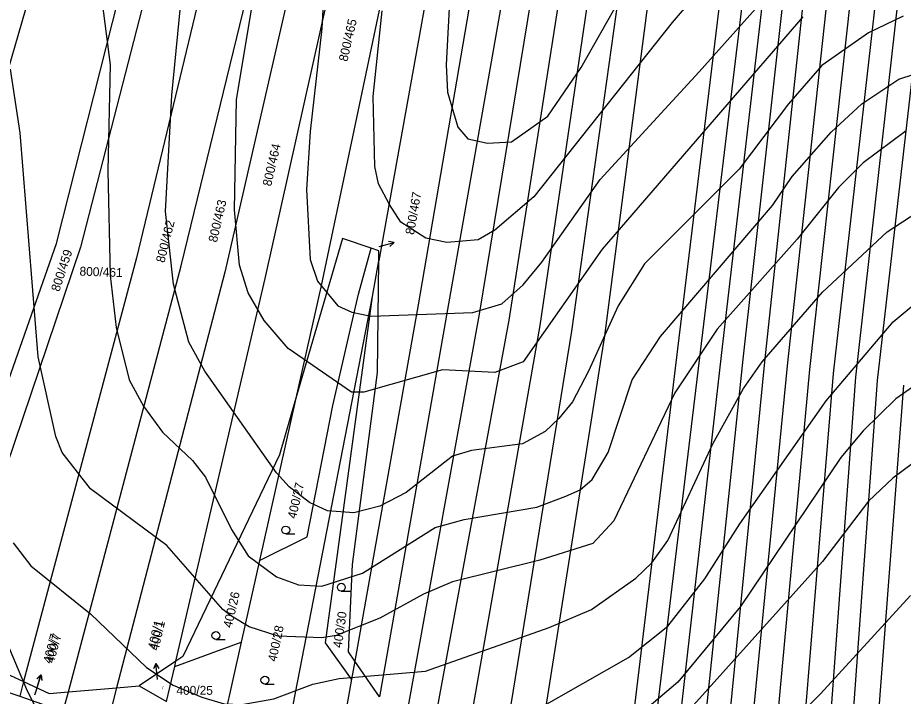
# Model space of a CAD drawing. Extents: x -555860 to -552701, y -1187050 to -1182291.
# Drawn here: x -555176.2 to -555007.3, y -1186234.6 to -1186105 of the extents above; entities that cross this region are included whole.
import ezdxf

# ---------------------------------------------------------------- set-up
doc = ezdxf.new("R2010")
doc.units = 0
for name, color, linetype in [('LEG_2b', 7, 'Continuous'), ('Level 16', 7, 'Continuous'), ('Level 25', 7, 'Continuous'), ('Level 40', 7, 'Continuous'), ('Level 41', 7, 'Continuous'), ('navrh_BV', 7, 'Continuous'), ('stav_BV', 7, 'Continuous')]:
    doc.layers.add(name, color=color, linetype=linetype)

msp = doc.modelspace()

# ---------------------------------------------------------------- linework, layer by layer
at = {"layer": 'Level 16'}
for p, q in [((-555107.26, -1186148.7), (-555104.35, -1186147.96)), ((-555104.35, -1186147.96), (-555105.45, -1186147.72)), ((-555104.35, -1186147.96), (-555105.2, -1186148.69)), ((-555149.86, -1186228.3), (-555150.25, -1186229.34)), ((-555149.54, -1186231.28), (-555149.86, -1186228.3)), ((-555149.86, -1186228.3), (-555149.25, -1186229.24)), ((-555172.61, -1186233.32), (-555171.74, -1186230.45)), ((-555171.74, -1186230.45), (-555172.51, -1186231.26)), ((-555171.74, -1186230.45), (-555171.55, -1186231.55))]:
    msp.add_line(p, q, dxfattribs=at)
for points in [[(-555149.53, -1186231.37), (-555149.54, -1186231.28)], [(-555172.89, -1186234.27), (-555172.61, -1186233.32)]]:
    msp.add_lwpolyline(points, dxfattribs=at)
at = {"layer": 'Level 25'}
for p, q in [((-555125.05, -1186203.58), (-555123.3, -1186203.58)), ((-555114.46, -1186214.51), (-555112.71, -1186214.51)), ((-555138.38, -1186223.73), (-555136.63, -1186223.73)), ((-555129.03, -1186232.24), (-555127.28, -1186232.24))]:
    msp.add_line(p, q, dxfattribs=at)
for centre in [(-555125.05, -1186202.83), (-555114.46, -1186213.76), (-555138.38, -1186222.98), (-555129.03, -1186231.49)]:
    msp.add_circle(centre, 0.75, dxfattribs=at)
at = {"layer": 'Level 40'}
for points in [[(-555026.4, -1186104.85), (-555064.67, -1186149.22), (-555079.79, -1186170.71), (-555085.19, -1186172.79), (-555095.18, -1186172.24), (-555110.15, -1186176.53), (-555112.51, -1186176.53), (-555124.57, -1186168.21), (-555129.15, -1186162.81), (-555132.2, -1186157.54), (-555133.86, -1186152.27), (-555134.83, -1186141.73), (-555134.42, -1186120.66), (-555130.26, -1186095.42)], [(-555216.36, -1186104.57), (-555208.74, -1186114.83), (-555204.3, -1186123.71), (-555203.74, -1186141.73), (-555200.42, -1186171.68), (-555198.48, -1186181.67), (-555194.87, -1186191.65), (-555190.02, -1186201.91), (-555181.14, -1186217.72), (-555174.35, -1186233.52), (-555167.69, -1186246.56), (-555164.64, -1186248.22), (-555153.69, -1186250.72)], [(-555153.69, -1186250.72), (-555143.43, -1186258.34), (-555141.77, -1186258.9), (-555139.13, -1186258.62), (-555137.61, -1186257.65), (-555130.67, -1186247.94), (-555126.51, -1186243.37), (-555120.14, -1186238.93), (-555118.33, -1186238.24), (-555109.78, -1186238.16), (-555102.51, -1186240.96), (-555094.86, -1186242.64), (-555089.83, -1186242.26), (-555085.84, -1186242.07), (-555059.68, -1186227.14), (-555052.19, -1186221.18), (-555045.12, -1186212.17), (-555038.47, -1186201.63), (-555021.97, -1186178.2), (-555009.21, -1186163.08), (-555000.89, -1186156.15)]]:
    msp.add_lwpolyline(points, dxfattribs=at)
at = {"layer": 'Level 41'}
for points in [[(-555090.74, -1186044.12), (-555094.48, -1186114), (-555094.21, -1186119.27), (-555092.26, -1186125.93), (-555090.32, -1186128.14), (-555086.58, -1186128.98), (-555082, -1186128.7), (-555075.07, -1186123.84), (-555068.69, -1186114.55), (-555061.2, -1186101.24)], [(-555117.22, -1186089.32), (-555118.19, -1186107.07), (-555120.41, -1186126.76), (-555121.1, -1186137.85), (-555120.41, -1186151.16), (-555119.03, -1186155.32), (-555115.14, -1186160.03), (-555112.46, -1186161.26), (-555108.77, -1186161.98), (-555089.35, -1186161.28), (-555083.81, -1186159.62), (-555079.79, -1186156.01), (-555076.18, -1186151.72), (-555065.09, -1186135.91), (-555046.23, -1186115.39), (-555027.93, -1186094.87)], [(-555042.49, -1186095.56), (-555051.36, -1186105.96), (-555077.71, -1186139.24), (-555085.19, -1186145.61), (-555088.38, -1186147.42), (-555094.34, -1186147.97), (-555098.36, -1186147.14), (-555103.08, -1186144.09), (-555105.28, -1186140.71), (-555107.38, -1186136.74), (-555108.07, -1186133.41), (-555108.35, -1186120.1), (-555106.69, -1186103.74)], [(-555007.27, -1186104.71), (-555013.92, -1186107.9), (-555022.8, -1186114.14), (-555029.18, -1186121.49), (-555038.6, -1186133.97), (-555056.63, -1186151.99), (-555061.62, -1186160.03), (-555067.31, -1186172.51), (-555070.38, -1186178.34), (-555072.99, -1186181.53), (-555075.58, -1186184.03), (-555079.92, -1186186.38), (-555089.63, -1186187.63), (-555093.23, -1186188.74), (-555102.11, -1186195.67), (-555107.1, -1186198.3), (-555112.09, -1186199.55), (-555117.08, -1186199.14), (-555120.55, -1186197.61), (-555124.43, -1186194.56), (-555126.79, -1186191.93), (-555140.52, -1186172.51), (-555143.57, -1186166.97), (-555146.48, -1186155.87), (-555148.01, -1186142.01), (-555146.76, -1186119.82), (-555144.82, -1186099.58)], [(-555160.34, -1186100.13), (-555158.54, -1186114), (-555158.96, -1186134.24), (-555158.54, -1186154.21), (-555157.43, -1186164.19), (-555154.94, -1186174.18), (-555152.17, -1186179.17), (-555148.56, -1186184.16), (-555142.87, -1186189.57), (-555140.38, -1186192.76), (-555135.39, -1186202.74), (-555132.2, -1186207.73), (-555126.79, -1186211.75), (-555122.63, -1186213.28), (-555118.19, -1186213.56), (-555110.43, -1186211.06), (-555096.56, -1186202.32), (-555091.02, -1186200.8), (-555077.15, -1186198.44), (-555071.6, -1186196.36), (-555068.89, -1186195.17), (-555066.61, -1186193.17), (-555063.56, -1186188.04), (-555058.99, -1186174.18), (-555053.58, -1186165.86), (-555032.23, -1186140.9), (-555028.48, -1186135.35), (-555020.99, -1186126.9), (-555015.17, -1186121.49), (-555008.1, -1186116.77), (-554993.68, -1186112.06)], [(-555006.71, -1186126.62), (-555014.89, -1186132.72), (-555019.61, -1186137.43), (-555027.51, -1186147.28), (-555042.76, -1186164.47), (-555050.81, -1186176.67), (-555062.45, -1186201.08), (-555066.47, -1186205.38), (-555076.6, -1186208.56), (-555093.23, -1186212.72), (-555098.78, -1186215.08), (-555107.1, -1186219.66), (-555115.42, -1186222.98), (-555118.19, -1186223.4), (-555126.51, -1186223.12), (-555132.06, -1186221.32), (-555135.42, -1186219.31), (-555137.05, -1186217.99), (-555147.73, -1186205.79), (-555162.29, -1186194.98), (-555167.69, -1186188.04), (-555168.94, -1186184.99), (-555172.27, -1186169.74), (-555175.74, -1186127.03), (-555177.54, -1186114.83)], [(-555022.66, -1186157.4), (-555010.32, -1186145.89), (-554999.92, -1186139.1), (-554992.85, -1186135.91), (-554988.41, -1186134.52), (-554979.54, -1186133.13), (-554969.83, -1186134.11), (-554962.07, -1186137.16), (-554952.36, -1186144.37), (-554946.81, -1186150.61), (-554937.66, -1186166.14), (-554932.12, -1186179.45), (-554927.54, -1186194.98), (-554924.49, -1186210.51), (-554918.94, -1186246), (-554914.92, -1186259.31), (-554911.32, -1186265.97), (-554901.89, -1186275.68), (-554896.2, -1186279.42), (-554865.84, -1186292.18), (-554856.13, -1186294.12), (-554852.25, -1186294.39)], [(-555177.02, -1186205.31), (-555173.66, -1186209.67), (-555162.29, -1186218.82), (-555151.61, -1186229.09), (-555146.55, -1186232.43), (-555141.07, -1186234.77), (-555136.77, -1186236.02), (-555133.45, -1186236.16), (-555127.34, -1186235.05), (-555119.86, -1186232.28), (-555114.87, -1186231.17), (-555098.41, -1186229.77), (-555074.79, -1186221.46), (-555066.75, -1186217.99), (-555058.29, -1186212.03), (-555055.24, -1186209.12), (-555052.19, -1186204.82), (-555043.6, -1186186.38), (-555037.77, -1186175.84), (-555034.17, -1186170.71), (-555022.66, -1186157.4)], [(-554999.78, -1186171.54), (-555008.66, -1186177.78), (-555014.89, -1186183.88), (-555019.19, -1186189.01), (-555038.33, -1186217.44), (-555050.25, -1186231.86), (-555062.45, -1186242.26)], [(-555005.33, -1186189.98), (-555009.24, -1186192.94), (-555013.92, -1186197.33), (-555022.66, -1186208.84), (-555052.89, -1186242.53), (-555064.67, -1186251.13), (-555079.65, -1186259.87), (-555092.13, -1186270.96), (-555097.12, -1186273.87), (-555107.1, -1186277.48), (-555122.08, -1186279.14), (-555142.04, -1186283.02), (-555152.03, -1186283.99), (-555164.23, -1186282.33), (-555170.88, -1186279.56), (-555174.86, -1186276.58)], [(-555177.61, -1186289.9), (-555157.3, -1186295.09), (-555147.31, -1186298.55), (-555142.84, -1186299.26), (-555139.55, -1186299.11), (-555135.66, -1186297.86), (-555129.43, -1186293.01), (-555123.19, -1186290.51), (-555117.22, -1186289.82), (-555103.22, -1186293.01), (-555099.34, -1186292.87), (-555096.01, -1186291.9), (-555090.74, -1186287.74), (-555082.56, -1186279.14), (-555074.66, -1186272.9), (-555069.11, -1186269.57), (-555055.38, -1186263.33), (-555046.37, -1186257.79), (-555023.07, -1186234.08), (-555005.88, -1186215.36)]]:
    msp.add_lwpolyline(points, dxfattribs=at)
at = {"layer": 'navrh_BV'}
for p, q in [((-555122.97, -1186023.5), (-555153.54, -1186150.9)), ((-555136.26, -1186040.23), (-555164.18, -1186148.84)), ((-555168.8, -1186148.11), (-555145.21, -1186054.86)), ((-555145.01, -1186152.38), (-555124.49, -1186067.99)), ((-555117.16, -1186068.44), (-555136.65, -1186153.61)), ((-555128.98, -1186154.84), (-555109.93, -1186069.02)), ((-555100.12, -1186069.85), (-555118.35, -1186156.47)), ((-555092.74, -1186070.37), (-555107.3, -1186151.46)), ((-555084.56, -1186070.95), (-555099.78, -1186159.84)), ((-555078.41, -1186071.33), (-555094.23, -1186160.72)), ((-555088.1, -1186161.63), (-555073.34, -1186071.77)), ((-555082.47, -1186162.74), (-555068.31, -1186072.02)), ((-555063.2, -1186072.55), (-555076.56, -1186163.78)), ((-555186.79, -1186145.19), (-555166.19, -1186074.17)), ((-555070.51, -1186164.87), (-555057.66, -1186072.82)), ((-555052.27, -1186073.22), (-555064.25, -1186165.76)), ((-555050.26, -1186168.24), (-555038.82, -1186074.15)), ((-555034.62, -1186074.53), (-555046.03, -1186168.83)), ((-555041.95, -1186169.53), (-555030.91, -1186074.64)), ((-555027.23, -1186074.92), (-555037.87, -1186170.22)), ((-555033.7, -1186170.75), (-555023.48, -1186075.09)), ((-555018.96, -1186075.4), (-555029.4, -1186171.48)), ((-555025.1, -1186172.2), (-555014.44, -1186075.72)), ((-555009.55, -1186075.13), (-555020.66, -1186172.94)), ((-555016.34, -1186173.62), (-555005.31, -1186075.79)), ((-555001.03, -1186076.57), (-555012.25, -1186174.29)), ((-555194.89, -1186222.61), (-555168.8, -1186148.11)), ((-555114.26, -1186147.16), (-555123.11, -1186177.66)), ((-555108.76, -1186149.02), (-555114.26, -1186147.16)), ((-555164.18, -1186148.84), (-555190.05, -1186224.85)), ((-555111.16, -1186157.8), (-555108.76, -1186149.02)), ((-555107.27, -1186149.53), (-555108.76, -1186149.02)), ((-555107.3, -1186151.46), (-555107.27, -1186149.53)), ((-555153.54, -1186150.9), (-555175.06, -1186231.77)), ((-555108.52, -1186158.28), (-555107.3, -1186151.46)), ((-555107.58, -1186172.76), (-555107.3, -1186151.46)), ((-555166.5, -1186233.72), (-555145.01, -1186152.38)), ((-555136.65, -1186153.61), (-555157.32, -1186232.94)), ((-555146, -1186227.85), (-555128.98, -1186154.84)), ((-555118.35, -1186156.47), (-555123.11, -1186177.66)), ((-555125.86, -1186247.68), (-555108.52, -1186158.28)), ((-555117.46, -1186224.35), (-555108.52, -1186158.28)), ((-555116.05, -1186179.09), (-555111.16, -1186157.8)), ((-555099.78, -1186159.84), (-555111.88, -1186227.84)), ((-555094.23, -1186160.72), (-555107.16, -1186234.67)), ((-555102.5, -1186241.2), (-555088.1, -1186161.63)), ((-555097.77, -1186245.64), (-555082.47, -1186162.74)), ((-555076.56, -1186163.78), (-555091.92, -1186251.14)), ((-555085.48, -1186257.19), (-555070.51, -1186164.87)), ((-555064.25, -1186165.76), (-555079.09, -1186259.62)), ((-555061.43, -1186260.68), (-555050.26, -1186168.24)), ((-555046.03, -1186168.83), (-555057.13, -1186260.95)), ((-555052.31, -1186261.05), (-555041.95, -1186169.53)), ((-555037.87, -1186170.22), (-555047.35, -1186261.3)), ((-555042.62, -1186261.45), (-555033.7, -1186170.75)), ((-555029.4, -1186171.48), (-555038.25, -1186261.63)), ((-555033.35, -1186261.86), (-555025.1, -1186172.2)), ((-555112.35, -1186209.4), (-555107.58, -1186172.76)), ((-555020.66, -1186172.94), (-555027.97, -1186262.21)), ((-555022.88, -1186262.45), (-555016.34, -1186173.62)), ((-555012.25, -1186174.29), (-555018.64, -1186262.69)), ((-555013.89, -1186263.01), (-555007.19, -1186175.17)), ((-555123.11, -1186177.66), (-555130.06, -1186208.64)), ((-555123.11, -1186177.66), (-555126.25, -1186188.5)), ((-555120.95, -1186204.12), (-555116.05, -1186179.09)), ((-555126.25, -1186188.5), (-555144.69, -1186226.97)), ((-555130.06, -1186208.64), (-555120.95, -1186204.12)), ((-555130.06, -1186208.64), (-555133.56, -1186224.25)), ((-555113.1, -1186226.08), (-555112.35, -1186209.4)), ((-555146.24, -1186228.9), (-555133.56, -1186224.25)), ((-555133.56, -1186224.25), (-555137.45, -1186241.58)), ((-555112.5, -1186231.3), (-555117.46, -1186224.35)), ((-555111.88, -1186227.84), (-555113.1, -1186226.08)), ((-555185.99, -1186226.72), (-555175.06, -1186231.77)), ((-555146, -1186227.85), (-555153.01, -1186232.57)), ((-555146.24, -1186228.9), (-555146, -1186227.85)), ((-555144.69, -1186226.97), (-555146, -1186227.85)), ((-555111.88, -1186227.84), (-555112.5, -1186231.3)), ((-555107.16, -1186234.67), (-555111.88, -1186227.84)), ((-555147.8, -1186235.58), (-555146.24, -1186228.9)), ((-555112.5, -1186231.3), (-555115.86, -1186250.2)), ((-555183.37, -1186232.05), (-555175.8, -1186234.56)), ((-555175.06, -1186231.77), (-555175.8, -1186234.56)), ((-555175.06, -1186231.77), (-555170.16, -1186234.03)), ((-555166.5, -1186233.72), (-555157.32, -1186232.94)), ((-555157.32, -1186232.94), (-555159.02, -1186239.48)), ((-555157.32, -1186232.94), (-555153.01, -1186232.57)), ((-555153.01, -1186232.57), (-555147.8, -1186235.58)), ((-555175.8, -1186234.56), (-555169.47, -1186236.75)), ((-555170.16, -1186234.03), (-555166.5, -1186233.72)), ((-555167.48, -1186237.42), (-555166.5, -1186233.72))]:
    msp.add_line(p, q, dxfattribs=at)
at = {"layer": 'stav_BV'}
for p, q in [((-555149.85, -1186228.29), (-555150.25, -1186229.34)), ((-555149.54, -1186231.28), (-555149.85, -1186228.29)), ((-555149.85, -1186228.29), (-555149.25, -1186229.24)), ((-555172.61, -1186233.32), (-555171.73, -1186230.45)), ((-555171.73, -1186230.45), (-555172.5, -1186231.26)), ((-555171.73, -1186230.45), (-555171.55, -1186231.55)), ((-555149.53, -1186231.37), (-555149.54, -1186231.28)), ((-555172.89, -1186234.27), (-555172.61, -1186233.32))]:
    msp.add_line(p, q, dxfattribs=at)

# ---------------------------------------------------------------- texts
at = {"layer": 'LEG_2b'}
for s, height, rotation, p in [('800/465', 1.7, 77, (-555113.32, -1186113.49)), ('800/464', 1.7, 77, (-555127.85, -1186137.31)), ('800/463', 1.7, 77, (-555138.19, -1186148.02)), ('800/462', 1.7, 76, (-555148.21, -1186151.91)), ('800/459', 1.7, 72, (-555168.26, -1186157.44)), ('800/461', 1.7, 358, (-555164.41, -1186154.26)), ('400/27', 1.7, 77, (-555123.09, -1186200.78)), ('400/26', 1.7, 77, (-555135.36, -1186221.61)), ('400/30', 1.7, 82, (-555114.38, -1186225.41)), ('400/1', 1.7, 77, (-555149.34, -1186225.96)), ('400/28', 1.7, 78, (-555126.86, -1186228.06)), ('400/7', 1.7, 75, (-555169.28, -1186228.36)), ('400/1', 0.2, 77, (-555148.5, -1186233.34))]:
    msp.add_text(s, height=height, rotation=rotation, dxfattribs=at).set_placement(p)
msp.add_text('400/25', height=1.7, dxfattribs=at).set_placement((-555145.91, -1186234.29))
at = {"layer": 'Level 16'}
for s, rotation, p in [('800/467', 80.1, (-555100.6, -1186146.54)), ('400/1', 76.5, (-555149.77, -1186225.79)), ('400/7', 74.7, (-555169.76, -1186228.44))]:
    msp.add_text(s, height=1.7, rotation=rotation, dxfattribs=at).set_placement(p)

doc.saveas('drawing.dxf')
